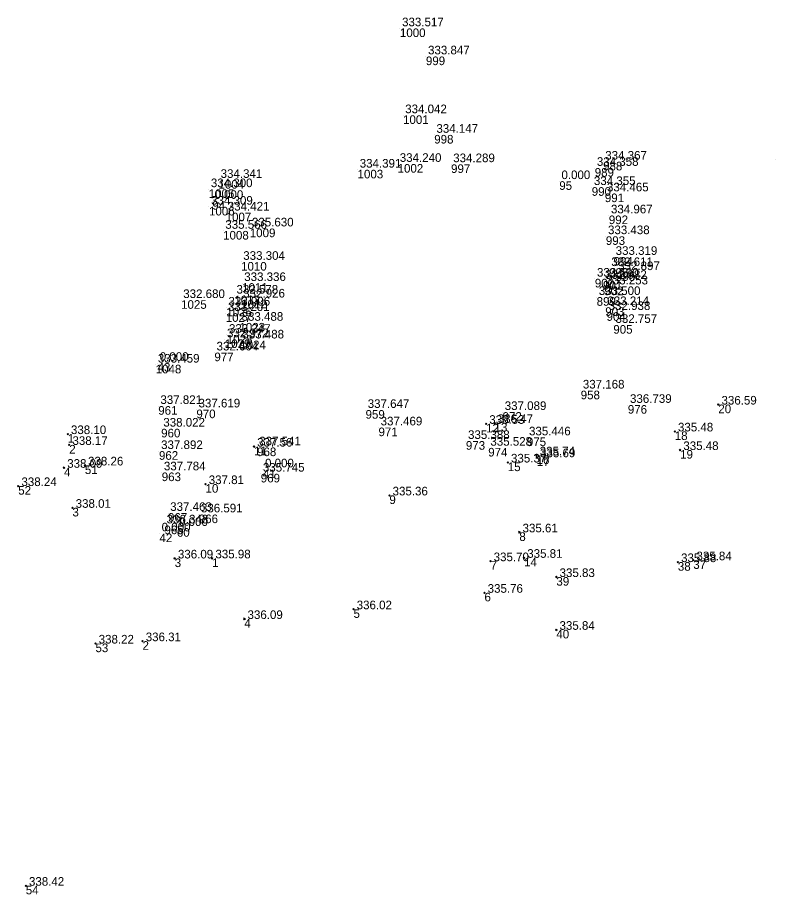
# Model space of a CAD drawing. Extents: x -829398 to -819400, y -1074439 to -1067977.
# Drawn here: x -825405.8 to -825300.3, y -1070179.7 to -1070057.6 of the extents above; entities that cross this region are included whole.
import ezdxf

# ---------------------------------------------------------------- set-up
doc = ezdxf.new("R2010")
doc.units = 0
doc.layers.add('Vrstva 60', color=7, linetype='Continuous')
doc.layers.add('Vrstva 61', color=7, linetype='Continuous')

msp = doc.modelspace()

# ---------------------------------------------------------------- linework, layer by layer
at = {"layer": 'Vrstva 60'}
for p, q in [((-825352.563, -1070059.115), (-825352.563, -1070059.115)), ((-825348.945, -1070063.024), (-825348.945, -1070063.024)), ((-825352.128, -1070071.215), (-825352.128, -1070071.215)), ((-825347.784, -1070073.943), (-825347.784, -1070073.943)), ((-825352.885, -1070077.994), (-825352.885, -1070077.994)), ((-825345.444, -1070078.037), (-825345.444, -1070078.037)), ((-825324.271, -1070077.681), (-825324.271, -1070077.681)), ((-825300.266, -1070077.344), (-825300.266, -1070077.344)), ((-825358.462, -1070078.793), (-825358.462, -1070078.793)), ((-825325.434, -1070078.547), (-825325.434, -1070078.547)), ((-825377.832, -1070080.223), (-825377.832, -1070080.223)), ((-825330.371, -1070080.39), (-825330.371, -1070080.39)), ((-825379.193, -1070081.515), (-825379.193, -1070081.515)), ((-825325.848, -1070081.217), (-825325.848, -1070081.217)), ((-825378.69, -1070083.149), (-825378.69, -1070083.149)), ((-825324.027, -1070082.098), (-825324.027, -1070082.098)), ((-825379.156, -1070083.953), (-825379.156, -1070083.953)), ((-825376.835, -1070084.766), (-825376.835, -1070084.766)), ((-825323.473, -1070085.16), (-825323.473, -1070085.16)), ((-825377.183, -1070087.308), (-825377.183, -1070087.308)), ((-825373.47, -1070086.979), (-825373.47, -1070086.979)), ((-825323.887, -1070088.058), (-825323.887, -1070088.058)), ((-825374.683, -1070091.634), (-825374.683, -1070091.634)), ((-825322.823, -1070090.943), (-825322.823, -1070090.943)), ((-825323.431, -1070092.502), (-825323.431, -1070092.502)), ((-825325.42, -1070093.972), (-825325.42, -1070093.972)), ((-825322.466, -1070093.064), (-825322.466, -1070093.064)), ((-825374.545, -1070094.581), (-825374.545, -1070094.581)), ((-825324.292, -1070094.286), (-825324.292, -1070094.286)), ((-825324.116, -1070095.057), (-825324.116, -1070095.057)), ((-825375.622, -1070096.335), (-825375.622, -1070096.335)), ((-825325.167, -1070096.528), (-825325.167, -1070096.528)), ((-825383.039, -1070096.951), (-825383.039, -1070096.951)), ((-825374.676, -1070096.88), (-825374.676, -1070096.88)), ((-825376.818, -1070098.766), (-825376.818, -1070098.766)), ((-825376.739, -1070098), (-825376.739, -1070098)), ((-825323.971, -1070097.938), (-825323.971, -1070097.938)), ((-825323.791, -1070098.62), (-825323.791, -1070098.62)), ((-825374.911, -1070100.118), (-825374.911, -1070100.118)), ((-825322.846, -1070100.414), (-825322.846, -1070100.414)), ((-825376.945, -1070102.408), (-825376.945, -1070102.408)), ((-825376.669, -1070101.791), (-825376.669, -1070101.791)), ((-825374.802, -1070102.58), (-825374.802, -1070102.58)), ((-825378.401, -1070104.248), (-825378.401, -1070104.248)), ((-825386.573, -1070105.942), (-825386.573, -1070105.942)), ((-825386.317, -1070105.699), (-825386.317, -1070105.699)), ((-825327.39, -1070109.549), (-825327.39, -1070109.549)), ((-825386.219, -1070111.701), (-825386.219, -1070111.701)), ((-825380.91, -1070112.182), (-825380.91, -1070112.182)), ((-825357.35, -1070112.254), (-825357.35, -1070112.254)), ((-825338.267, -1070112.54), (-825338.267, -1070112.54)), ((-825320.824, -1070111.552), (-825320.824, -1070111.552)), ((-825308.226, -1070111.486), (-825308.326, -1070111.386)), ((-825308.226, -1070111.486), (-825308.326, -1070111.586)), ((-825308.226, -1070111.486), (-825308.126, -1070111.386)), ((-825308.226, -1070111.486), (-825308.126, -1070111.586)), ((-825385.814, -1070114.855), (-825385.814, -1070114.855)), ((-825355.55, -1070114.685), (-825355.55, -1070114.685)), ((-825340.567, -1070114.166), (-825340.667, -1070114.066)), ((-825340.567, -1070114.166), (-825340.667, -1070114.266)), ((-825340.567, -1070114.166), (-825340.467, -1070114.066)), ((-825340.567, -1070114.166), (-825340.467, -1070114.266)), ((-825339.383, -1070114.045), (-825339.483, -1070113.945)), ((-825339.383, -1070114.045), (-825339.483, -1070114.145)), ((-825339.383, -1070114.045), (-825339.283, -1070113.945)), ((-825339.383, -1070114.045), (-825339.283, -1070114.145)), ((-825398.822, -1070115.593), (-825398.922, -1070115.493)), ((-825398.822, -1070115.593), (-825398.922, -1070115.693)), ((-825398.822, -1070115.593), (-825398.722, -1070115.493)), ((-825398.822, -1070115.593), (-825398.722, -1070115.693)), ((-825334.885, -1070116.07), (-825334.885, -1070116.07)), ((-825314.289, -1070115.224), (-825314.389, -1070115.124)), ((-825314.289, -1070115.224), (-825314.389, -1070115.324)), ((-825314.289, -1070115.224), (-825314.189, -1070115.124)), ((-825314.289, -1070115.224), (-825314.189, -1070115.324)), ((-825398.613, -1070117.103), (-825398.713, -1070117.003)), ((-825398.613, -1070117.103), (-825398.713, -1070117.203)), ((-825398.613, -1070117.103), (-825398.513, -1070117.003)), ((-825398.613, -1070117.103), (-825398.513, -1070117.203)), ((-825372.891, -1070117.336), (-825372.991, -1070117.236)), ((-825372.891, -1070117.336), (-825372.991, -1070117.436)), ((-825372.891, -1070117.336), (-825372.791, -1070117.236)), ((-825372.891, -1070117.336), (-825372.791, -1070117.436)), ((-825343.379, -1070116.572), (-825343.379, -1070116.572)), ((-825386.12, -1070117.973), (-825386.12, -1070117.973)), ((-825372.457, -1070117.463), (-825372.457, -1070117.463)), ((-825340.267, -1070117.514), (-825340.267, -1070117.514)), ((-825333.535, -1070118.568), (-825333.635, -1070118.468)), ((-825333.535, -1070118.568), (-825333.635, -1070118.668)), ((-825333.535, -1070118.568), (-825333.435, -1070118.468)), ((-825333.535, -1070118.568), (-825333.435, -1070118.668)), ((-825313.541, -1070117.816), (-825313.641, -1070117.716)), ((-825313.541, -1070117.816), (-825313.641, -1070117.916)), ((-825313.541, -1070117.816), (-825313.441, -1070117.716)), ((-825313.541, -1070117.816), (-825313.441, -1070117.916)), ((-825396.437, -1070119.96), (-825396.537, -1070119.86)), ((-825396.437, -1070119.96), (-825396.337, -1070119.86)), ((-825337.542, -1070119.55), (-825337.642, -1070119.45)), ((-825337.542, -1070119.55), (-825337.642, -1070119.65)), ((-825337.542, -1070119.55), (-825337.442, -1070119.45)), ((-825337.542, -1070119.55), (-825337.442, -1070119.65)), ((-825333.491, -1070118.822), (-825333.591, -1070118.722)), ((-825333.491, -1070118.822), (-825333.591, -1070118.922)), ((-825333.491, -1070118.822), (-825333.391, -1070118.722)), ((-825333.491, -1070118.822), (-825333.391, -1070118.922)), ((-825399.34, -1070120.283), (-825399.44, -1070120.183)), ((-825399.34, -1070120.283), (-825399.44, -1070120.383)), ((-825399.34, -1070120.283), (-825399.24, -1070120.183)), ((-825399.34, -1070120.283), (-825399.24, -1070120.383)), ((-825396.437, -1070119.96), (-825396.537, -1070120.06)), ((-825396.437, -1070119.96), (-825396.337, -1070120.06)), ((-825385.73, -1070120.943), (-825385.73, -1070120.943)), ((-825371.651, -1070120.526), (-825371.651, -1070120.526)), ((-825371.944, -1070121.124), (-825371.944, -1070121.124)), ((-825405.715, -1070122.831), (-825405.815, -1070122.731)), ((-825405.715, -1070122.831), (-825405.815, -1070122.931)), ((-825405.715, -1070122.831), (-825405.615, -1070122.731)), ((-825405.715, -1070122.831), (-825405.615, -1070122.931)), ((-825379.633, -1070122.558), (-825379.733, -1070122.458)), ((-825379.633, -1070122.558), (-825379.733, -1070122.658)), ((-825379.633, -1070122.558), (-825379.533, -1070122.458)), ((-825379.633, -1070122.558), (-825379.533, -1070122.658)), ((-825354.031, -1070124.132), (-825354.131, -1070124.032)), ((-825354.031, -1070124.132), (-825354.131, -1070124.232)), ((-825354.031, -1070124.132), (-825353.931, -1070124.032)), ((-825354.031, -1070124.132), (-825353.931, -1070124.232)), ((-825398.166, -1070125.859), (-825398.266, -1070125.759)), ((-825398.166, -1070125.859), (-825398.266, -1070125.959)), ((-825398.166, -1070125.859), (-825398.066, -1070125.759)), ((-825398.166, -1070125.859), (-825398.066, -1070125.959)), ((-825384.857, -1070126.591), (-825384.857, -1070126.591)), ((-825380.574, -1070126.795), (-825380.574, -1070126.795)), ((-825385.355, -1070128.333), (-825385.355, -1070128.333)), ((-825386.046, -1070129.439), (-825386.046, -1070129.439)), ((-825383.624, -1070128.69), (-825383.624, -1070128.69)), ((-825335.932, -1070129.274), (-825336.032, -1070129.174)), ((-825335.932, -1070129.274), (-825336.032, -1070129.374)), ((-825335.932, -1070129.274), (-825335.832, -1070129.174)), ((-825335.932, -1070129.274), (-825335.832, -1070129.374)), ((-825383.926, -1070132.911), (-825384.026, -1070132.811)), ((-825383.926, -1070132.911), (-825384.026, -1070133.011)), ((-825383.926, -1070132.911), (-825383.826, -1070132.811)), ((-825383.926, -1070132.911), (-825383.826, -1070133.011)), ((-825378.703, -1070132.896), (-825378.803, -1070132.796)), ((-825378.703, -1070132.896), (-825378.803, -1070132.996)), ((-825378.703, -1070132.896), (-825378.603, -1070132.796)), ((-825378.703, -1070132.896), (-825378.603, -1070132.996)), ((-825339.959, -1070133.293), (-825340.059, -1070133.193)), ((-825339.959, -1070133.293), (-825340.059, -1070133.393)), ((-825339.959, -1070133.293), (-825339.859, -1070133.193)), ((-825339.959, -1070133.293), (-825339.859, -1070133.393)), ((-825335.279, -1070132.821), (-825335.379, -1070132.721)), ((-825335.279, -1070132.821), (-825335.379, -1070132.921)), ((-825335.279, -1070132.821), (-825335.179, -1070132.721)), ((-825335.279, -1070132.821), (-825335.179, -1070132.921)), ((-825311.711, -1070133.162), (-825311.811, -1070133.062)), ((-825311.711, -1070133.162), (-825311.811, -1070133.262)), ((-825311.711, -1070133.162), (-825311.611, -1070133.062)), ((-825311.711, -1070133.162), (-825311.611, -1070133.262)), ((-825313.856, -1070133.419), (-825313.956, -1070133.319)), ((-825313.856, -1070133.419), (-825313.956, -1070133.519)), ((-825313.856, -1070133.419), (-825313.756, -1070133.319)), ((-825313.856, -1070133.419), (-825313.756, -1070133.519)), ((-825330.774, -1070135.497), (-825330.874, -1070135.397)), ((-825330.774, -1070135.497), (-825330.874, -1070135.597)), ((-825330.774, -1070135.497), (-825330.674, -1070135.397)), ((-825330.774, -1070135.497), (-825330.674, -1070135.597)), ((-825340.793, -1070137.688), (-825340.893, -1070137.588)), ((-825340.793, -1070137.688), (-825340.893, -1070137.788)), ((-825340.793, -1070137.688), (-825340.693, -1070137.588)), ((-825340.793, -1070137.688), (-825340.693, -1070137.788)), ((-825359.03, -1070139.987), (-825359.13, -1070139.887)), ((-825359.03, -1070139.987), (-825359.13, -1070140.087)), ((-825359.03, -1070139.987), (-825358.93, -1070139.887)), ((-825359.03, -1070139.987), (-825358.93, -1070140.087)), ((-825374.23, -1070141.338), (-825374.33, -1070141.238)), ((-825374.23, -1070141.338), (-825374.33, -1070141.438)), ((-825374.23, -1070141.338), (-825374.13, -1070141.238)), ((-825374.23, -1070141.338), (-825374.13, -1070141.438)), ((-825330.784, -1070142.845), (-825330.884, -1070142.745)), ((-825330.784, -1070142.845), (-825330.884, -1070142.945)), ((-825330.784, -1070142.845), (-825330.684, -1070142.745)), ((-825330.784, -1070142.845), (-825330.684, -1070142.945)), ((-825394.963, -1070144.756), (-825395.063, -1070144.656)), ((-825394.963, -1070144.756), (-825395.063, -1070144.856)), ((-825394.963, -1070144.756), (-825394.863, -1070144.656)), ((-825394.963, -1070144.756), (-825394.863, -1070144.856)), ((-825388.407, -1070144.432), (-825388.507, -1070144.332)), ((-825388.407, -1070144.432), (-825388.507, -1070144.532)), ((-825388.407, -1070144.432), (-825388.307, -1070144.332)), ((-825388.407, -1070144.432), (-825388.307, -1070144.532)), ((-825404.668, -1070178.478), (-825404.768, -1070178.378)), ((-825404.668, -1070178.478), (-825404.768, -1070178.578)), ((-825404.668, -1070178.478), (-825404.568, -1070178.378)), ((-825404.668, -1070178.478), (-825404.568, -1070178.578))]:
    msp.add_line(p, q, dxfattribs=at)

# ---------------------------------------------------------------- texts
for s, p in [('1000', (-825352.563, -1070060.315)), ('999', (-825348.945, -1070064.224)), ('1001', (-825352.128, -1070072.415)), ('998', (-825347.784, -1070075.143)), ('1002', (-825352.885, -1070079.194)), ('997', (-825345.444, -1070079.237)), ('988', (-825324.271, -1070078.881)), ('1003', (-825358.462, -1070079.993)), ('989', (-825325.434, -1070079.747)), ('1004', (-825377.832, -1070081.423)), ('95', (-825330.371, -1070081.59)), ('1005', (-825379.193, -1070082.715)), ('990', (-825325.848, -1070082.417)), ('94', (-825378.69, -1070084.349)), ('991', (-825324.027, -1070083.298)), ('1006', (-825379.156, -1070085.153)), ('1007', (-825376.835, -1070085.966)), ('992', (-825323.473, -1070086.36)), ('1008', (-825377.183, -1070088.508)), ('1009', (-825373.47, -1070088.179)), ('993', (-825323.887, -1070089.258)), ('1010', (-825374.683, -1070092.834)), ('994', (-825322.823, -1070092.143)), ('996', (-825323.431, -1070093.702)), ('900', (-825325.42, -1070095.172)), ('995', (-825322.466, -1070094.264)), ('1011', (-825374.545, -1070095.781)), ('901', (-825324.292, -1070095.486)), ('902', (-825324.116, -1070096.257)), ('1013', (-825375.622, -1070097.535)), ('899', (-825325.167, -1070097.728)), ('1025', (-825383.039, -1070098.151)), ('1012', (-825374.676, -1070098.08)), ('1027', (-825376.818, -1070099.966)), ('1026', (-825376.739, -1070099.2)), ('903', (-825323.971, -1070099.138)), ('904', (-825323.791, -1070099.82)), ('1023', (-825374.911, -1070101.318)), ('905', (-825322.846, -1070101.614)), ('1029', (-825376.945, -1070103.608)), ('1028', (-825376.669, -1070102.991)), ('1024', (-825374.802, -1070103.78)), ('977', (-825378.401, -1070105.448)), ('1048', (-825386.573, -1070107.142)), ('43', (-825386.317, -1070106.899)), ('958', (-825327.39, -1070110.749)), ('961', (-825386.219, -1070112.901)), ('970', (-825380.91, -1070113.382)), ('959', (-825357.35, -1070113.454)), ('972', (-825338.267, -1070113.74)), ('976', (-825320.824, -1070112.752)), ('20', (-825308.226, -1070112.686)), ('960', (-825385.814, -1070116.055)), ('971', (-825355.55, -1070115.885)), ('12', (-825340.567, -1070115.366)), ('13', (-825339.383, -1070115.245)), ('1', (-825398.822, -1070116.793)), ('975', (-825334.885, -1070117.27)), ('18', (-825314.289, -1070116.424)), ('2', (-825398.613, -1070118.303)), ('11', (-825372.891, -1070118.536)), ('973', (-825343.379, -1070117.772)), ('962', (-825386.12, -1070119.173)), ('968', (-825372.457, -1070118.663)), ('974', (-825340.267, -1070118.714)), ('16', (-825333.535, -1070119.768)), ('19', (-825313.541, -1070119.016)), ('15', (-825337.542, -1070120.75)), ('17', (-825333.491, -1070120.022)), ('4', (-825399.34, -1070121.483)), ('51', (-825396.437, -1070121.16)), ('963', (-825385.73, -1070122.143)), ('41', (-825371.651, -1070121.726)), ('969', (-825371.944, -1070122.324)), ('52', (-825405.715, -1070124.031)), ('10', (-825379.633, -1070123.758)), ('9', (-825354.031, -1070125.332)), ('3', (-825398.166, -1070127.059)), ('967', (-825384.857, -1070127.791)), ('966', (-825380.574, -1070127.995)), ('965', (-825385.355, -1070129.533)), ('42', (-825386.046, -1070130.639)), ('60', (-825383.624, -1070129.89)), ('8', (-825335.932, -1070130.474)), ('3', (-825383.926, -1070134.111)), ('1', (-825378.703, -1070134.096)), ('7', (-825339.959, -1070134.493)), ('14', (-825335.279, -1070134.021)), ('37', (-825311.711, -1070134.362)), ('38', (-825313.856, -1070134.619)), ('39', (-825330.774, -1070136.697)), ('6', (-825340.793, -1070138.888)), ('5', (-825359.03, -1070141.187)), ('4', (-825374.23, -1070142.538)), ('40', (-825330.784, -1070144.045)), ('53', (-825394.963, -1070145.956)), ('2', (-825388.407, -1070145.632)), ('54', (-825404.668, -1070179.678))]:
    msp.add_text(s, height=1.2, dxfattribs=at).set_placement(p)
at = {"layer": 'Vrstva 61'}
for s, p in [('333.517', (-825352.263, -1070058.815)), ('333.847', (-825348.645, -1070062.724)), ('334.042', (-825351.828, -1070070.915)), ('334.147', (-825347.484, -1070073.643)), ('334.240', (-825352.585, -1070077.694)), ('334.289', (-825345.144, -1070077.737)), ('334.358', (-825325.134, -1070078.247)), ('334.367', (-825323.971, -1070077.381)), ('334.391', (-825358.162, -1070078.493)), ('334.341', (-825377.532, -1070079.923)), ('0.000', (-825330.071, -1070080.09)), ('334.300', (-825378.893, -1070081.215)), ('334.355', (-825325.548, -1070080.917)), ('334.465', (-825323.727, -1070081.798)), ('0.000', (-825378.39, -1070082.849)), ('334.309', (-825378.856, -1070083.653)), ('334.421', (-825376.535, -1070084.466)), ('334.967', (-825323.173, -1070084.86)), ('335.630', (-825373.17, -1070086.679)), ('335.566', (-825376.883, -1070087.008)), ('333.438', (-825323.587, -1070087.758)), ('333.304', (-825374.383, -1070091.334)), ('333.319', (-825322.523, -1070090.643)), ('332.611', (-825323.131, -1070092.202)), ('332.897', (-825322.166, -1070092.764)), ('333.590', (-825325.12, -1070093.672)), ('332.982', (-825323.992, -1070093.986)), ('333.336', (-825374.245, -1070094.281)), ('333.253', (-825323.816, -1070094.757)), ('332.680', (-825382.739, -1070096.651)), ('332.578', (-825375.322, -1070096.035)), ('332.926', (-825374.376, -1070096.58)), ('333.500', (-825324.867, -1070096.228)), ('333.006', (-825376.439, -1070097.7)), ('333.214', (-825323.671, -1070097.638)), ('333.201', (-825376.518, -1070098.466)), ('332.938', (-825323.491, -1070098.32)), ('333.488', (-825374.611, -1070099.818)), ('332.757', (-825322.546, -1070100.114)), ('333.247', (-825376.369, -1070101.491)), ('332.972', (-825376.645, -1070102.108)), ('333.488', (-825374.502, -1070102.28)), ('332.604', (-825378.101, -1070103.948)), ('333.459', (-825386.273, -1070105.642)), ('0.000', (-825386.017, -1070105.399)), ('337.168', (-825327.09, -1070109.249)), ('336.739', (-825320.524, -1070111.252)), ('337.821', (-825385.919, -1070111.401)), ('337.619', (-825380.61, -1070111.882)), ('337.647', (-825357.05, -1070111.954)), ('337.089', (-825337.967, -1070112.24)), (' 336.59', (-825308.226, -1070111.486)), ('338.022', (-825385.514, -1070114.555)), ('337.469', (-825355.25, -1070114.385)), (' 336.53', (-825340.567, -1070114.166)), (' 336.47', (-825339.383, -1070114.045)), (' 338.10', (-825398.822, -1070115.593)), ('335.446', (-825334.585, -1070115.77)), (' 335.48', (-825314.289, -1070115.224)), (' 338.17', (-825398.613, -1070117.103)), (' 337.56', (-825372.891, -1070117.336)), ('337.541', (-825372.157, -1070117.163)), ('335.388', (-825343.079, -1070116.272)), ('335.528', (-825339.967, -1070117.214)), ('337.892', (-825385.82, -1070117.673)), (' 335.74', (-825333.535, -1070118.568)), (' 335.48', (-825313.541, -1070117.816)), (' 335.37', (-825337.542, -1070119.55)), (' 335.69', (-825333.491, -1070118.822)), (' 338.09', (-825399.34, -1070120.283)), (' 338.26', (-825396.437, -1070119.96)), ('337.784', (-825385.43, -1070120.643)), ('335.745', (-825371.644, -1070120.824)), ('0.000', (-825371.351, -1070120.226)), (' 338.24', (-825405.715, -1070122.831)), (' 337.81', (-825379.633, -1070122.558)), (' 335.36', (-825354.031, -1070124.132)), (' 338.01', (-825398.166, -1070125.859)), ('337.463', (-825384.557, -1070126.291)), ('336.591', (-825380.274, -1070126.495)), ('336.343', (-825385.055, -1070128.033)), ('0.000', (-825383.324, -1070128.39)), ('0.000', (-825385.746, -1070129.139)), (' 335.61', (-825335.932, -1070129.274)), (' 336.09', (-825383.926, -1070132.911)), (' 335.98', (-825378.703, -1070132.896)), (' 335.70', (-825339.959, -1070133.293)), (' 335.81', (-825335.279, -1070132.821)), (' 335.84', (-825311.711, -1070133.162)), (' 335.88', (-825313.856, -1070133.419)), (' 335.83', (-825330.774, -1070135.497)), (' 335.76', (-825340.793, -1070137.688)), (' 336.02', (-825359.03, -1070139.987)), (' 336.09', (-825374.23, -1070141.338)), (' 335.84', (-825330.784, -1070142.845)), (' 338.22', (-825394.963, -1070144.756)), (' 336.31', (-825388.407, -1070144.432)), (' 338.42', (-825404.668, -1070178.478))]:
    msp.add_text(s, height=1.2, dxfattribs=at).set_placement(p)

doc.saveas('drawing.dxf')
